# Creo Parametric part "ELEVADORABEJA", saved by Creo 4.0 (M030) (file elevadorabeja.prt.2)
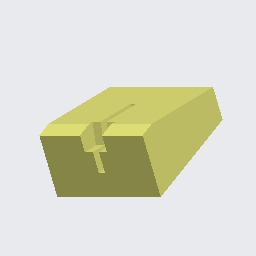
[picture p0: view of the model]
Units: millimeter Newton Second (mmNs); MM, TONNE, SECS

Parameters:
  MODELED_BY = "aj"

Created from: MMNS_PART_SOLID.PRT

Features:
  1. datum plane "RIGHT"
  2. datum plane "TOP"
  3. datum plane "FRONT"
  4. coordinate system
  5. extrusion "Extrude 1"
  6. extruded cut "Extrude 2"
  7. extruded cut "Extrude 3"
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
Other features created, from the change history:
  extruded cut "Extrude 4" (2 times)

Surfaces: 15 plane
